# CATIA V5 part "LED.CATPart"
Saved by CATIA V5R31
Part number: LED
Source: Unknown
Bounding box of the stored display mesh (mm): x -0.8 to 0.8, y -0.4 to 0.4, z 0 to 0.55
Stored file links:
  \\solize.local\damia\dept\DDE_Design\10_order\2305701_JAMA_変換検証STEP3_お手本モデル作成\work\03_東洋電装_スイッチ\10_CATIA_V5\LED.CATPart
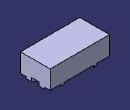
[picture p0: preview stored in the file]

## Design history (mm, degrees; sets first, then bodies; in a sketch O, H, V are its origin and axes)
WSupportSet1: ActiveGrid {3dwsupport RefPoint {point stored without definition}, 3DWOS ({wsupport Support xy-plane, RefPoint {3dwsupport}, GridIn {cartgrid Value 100, Stepbid1 0, Value 100, Stepbid2 0, Direction (1, 0, 0)}, GeometricData ({line type PtDir, Direction (1, 0, 0), Support xy-plane}; {line type PtDir, Direction (0, 1, 0), Support xy-plane})}; {wsupport Support yz-plane, RefPoint {3dwsupport}, GridIn {cartgrid Value 100, Stepbid1 0, Value 100, Stepbid2 0, Direction (0, 1, 0)}, GeometricData ({line type PtDir, Direction (0, 1, 0), Support yz-plane}; {line type PtDir, Direction (0, 0, 1), Support yz-plane})}; {wsupport Support zx-plane, RefPoint {3dwsupport}, GridIn {cartgrid Value 100, Stepbid1 0, Value 100, Stepbid2 0, Direction (0, 0, 1)}, GeometricData ({line type PtDir, Direction (0, 0, 1), Support zx-plane}; {line type PtDir, Direction (1, 0, 0), Support zx-plane})}), GeometricData ({line type PtDir, RefPoint {point stored without definition}, Direction (1, 0, 0), Support xy-plane}; {line type PtDir, RefPoint {point stored without definition}, Direction (0, 1, 0), Support xy-plane}; {line type PtDir, RefPoint {point stored without definition}, Direction (0, 1, 0), Support yz-plane}; {line type PtDir, RefPoint {point stored without definition}, Direction (0, 0, 1), Support yz-plane}; {line type PtDir, RefPoint {point stored without definition}, Direction (0, 0, 1), Support zx-plane}; {line type PtDir, RefPoint {point stored without definition}, Direction (1, 0, 0), Support zx-plane})}
Body1 (main body)
  Solid1 "PartBody": solid without history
